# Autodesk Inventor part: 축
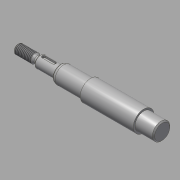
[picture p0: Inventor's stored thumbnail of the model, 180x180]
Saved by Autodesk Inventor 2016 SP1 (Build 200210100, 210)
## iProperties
Created: 2015-11
Part Number: 축
Material: 강철, 연강
Document SubType Name: Modeling
Designer: mduedu
Density: 1 g/cm^3
Appearance: 강철
Author: mduedu
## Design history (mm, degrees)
sketch "스케치1"
  geometry: L1 (-86, 0)-(86, 0); L2 (-86, 0)-(-86, 4); L3 (-86, 4)-(-70.732, 4); L4 (-70.732, 4)-(-69, 3); L5 (-69, 3)-(-67, 3); L6 (-67, 3)-(-67, 5); L7 (-67, 5)-(-49, 5); L8 (-49, 5)-(-49, 6.55); L9 (-47.355, 7.5)-(-23, 7.5); L10 (-23, 7.5)-(-23, 9); L11 (0, 0)-(0, 9); L12 (86, 4)-(70.732, 4); L13 (70.732, 4)-(69, 3); L14 (69, 3)-(67, 3); L15 (67, 3)-(67, 5); L16 (67, 5)-(49, 5); L17 (23, 7.5)-(23, 9); L18 (86, 0)-(86, 4); L19 (-23, 9)-(23, 9); L20 (-49, 6.55)-(-47.355, 7.5); L21 (47.355, 7.5)-(23, 7.5); L22 (49, 6.55)-(47.355, 7.5); L23 (49, 5)-(49, 6.55); 1 further point
  constraints: 46 end point, 10 symmetric about line, 6 perpendicular, 5 parallel, 2 midpoint, 1 coincident, 1 horizontal
  dimensions: "d0" = 172 distance of L1.start L1.end (derived); "d1" = 8 diameter of L3 L1; "d2" = 30 deg angle of L4 L5; "d3" = 6 diameter of L5 L1; "d4" = 10 diameter of L7 L1; "d5" = 15 diameter of L9 L1; "d6" = 18 diameter of L19 L1; "d8" = 18 distance of L6.end L7.end; "d9" = 46 distance of L10.end L17.end; "d10" = 2 distance of L4.end L5.end; "d11" = 17 distance from line of L4.end L2; "d16" = 13.1 diameter of L8.end L1; "d17" = 30 deg angle of L20 L9; "d18" = 26 distance between parallel lines of L10 L8
revolve "회전1" sketch "스케치1" stored, may be unused: angle "d12" = 90 deg
chamfer "모따기1" distance "d13" = 1; stored, may be unused: second distance "d14" = 2, angle "d15" = 45 deg
fillet "모깎기1" dims "d19" = 4, "d20" = 0.5
node "작업 평면1"
sketch "스케치2" dims "d23" = 12
  geometry: L1 (-5.5, 1.5)-(3.5, 1.5); L2 (3.5, 1.5)-(3.5, -1.5); L3 (3.5, -1.5)-(-5.5, -1.5); L4 (-5.5, -1.5)-(-5.5, 1.5); L5 (-9, -4)-(-9, 4) reference; 3 further points
  constraints: 8 end point, 2 midpoint, 2 parallel, 2 vertical alignment, 1 horizontal, 1 perpendicular, 4 other
  dimensions: "d21" = 3 distance between parallel lines of L3 L1; "d24" = 2 dimension on L5
extrude "돌출1" cut sketch "스케치2" distance "d25" = 1.8; taper "d26" = 0 deg
feature "스레드1" dims "d27" = 10, "d28" = 0
feature "스레드2" dims "d29" = 10, "d30" = 0
chamfer "모따기2" distance "d31" = 1; stored, may be unused: second distance "d32" = 2, angle "d33" = 45 deg
node "작업 평면2"
sketch "스케치3"
  geometry: C1 r 7.5 at (0, 0) reference; 1 further point
extrude "돌출2" cut sketch "스케치3" stored distance "d36" = 10; taper "d37" = 0 deg
chamfer "모따기3" distance "d38" = 1; stored, may be unused: second distance "d39" = 2, angle "d40" = 45 deg
node "솔리드1"
mirror "대칭1"
node "절단 모서리 투영1"
other parameters: "d35" = 16
